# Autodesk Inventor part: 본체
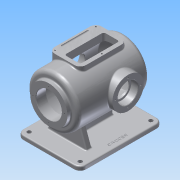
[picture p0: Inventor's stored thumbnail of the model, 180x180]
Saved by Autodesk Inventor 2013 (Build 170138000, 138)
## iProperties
Created: 2016-02
Part Number: 본체
Material: 알루미늄 6061
Document SubType Name: Modeling
Designer: mduedu
Density: 2.71 g/cm^3
Mass: 3760.55 g
Surface Area: 2685.54 cm^2
Volume: 1387.66 cm^3
Author: mduedu
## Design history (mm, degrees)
sketch "스케치2"
  geometry: L1 (0, 100)-(0, -100); L2 (65, -75.993)-(65, 100); L3 (65, 100)-(0, 100); A1 r 100 centre (0, 0) between (0, -100) and (65, -75.993); 2 further points
  constraints: 6 end point, 2 midpoint, 2 point on circle, 1 centre point, 1 coincident, 1 horizontal, 1 parallel, 1 vertical
  dimensions: "d3" = 200 distance of L1.start L1.end; "d5" = 130 diameter of L2 L1; "d6" = 100 radius of A1
revolve "회전1" sketch "스케치2" stored, may be unused: angle "d7" = 90 deg
sketch "스케치3"
  geometry: C1 r 47.5 at (0, 0); 1 further point
  constraints: 1 centre point, 1 coincident
  dimensions: "d8" = 95 diameter of C1
extrude "돌출2" join sketch "스케치3" distance "d10" = 10; taper "d11" = 0 deg
sketch "스케치5"
  geometry: L1 (47.5, 110)-(47.5, 100) reference; L2 (47.5, 100)-(65, 100) reference; L3 (65, 100)-(65, -75.993) reference; L4 (-65, -75.993)-(-65, 100) reference; L5 (-65, 100)-(-47.5, 100) reference; L6 (-47.5, 100)-(-47.5, 110) reference; L7 (-47.5, 110)-(47.5, 110) reference; L8 (55, 85)-(55, -71.239); L9 (0, 85)-(55, 85); L10 (0, 85)-(0, -90); A1 r 100 centre (0, 0) between (0, -100) and (65, -75.993) reference; A2 r 100 centre (0, 0) between (-65, -75.993) and (0, -100) reference; A3 r 90 centre (0, 0) between (0, -90) and (55, -71.239); 1 further point
  constraints: 6 end point, 2 point on circle, 1 centre point, 1 parallel, 1 perpendicular, 1 point on line, 1 vertical
  dimensions: "d13" = 10 distance between parallel lines of L3 L8; "d14" = 10 radial gap between concentric circles of A3 A1; "d15" = 15 distance between parallel lines of L9 L2
revolve "회전2" sketch "스케치5" stored, may be unused: angle "d16" = 90 deg
hole "구멍1" diameter "d19" = 65; stored, may be unused: countersink angle "d23" = 90 deg, drill point angle "d25" = 118 deg; dims "d17" = 10, "d18" = 10, "d20" = 6, "d21" = 4, "d22" = 2, "d24" = 8
node "작업 평면1"
sketch "스케치6"
  geometry: L1 (47.5, 110)-(-47.5, 110) reference; C1 r 40 at (0, -17); 1 further point
  constraints: 1 centre point, 1 vertical alignment
  dimensions: "d27" = 80 diameter of C1; "d29" = 127 distance from line of C1.centre L1
extrude "돌출3" join sketch "스케치6" stored distance "d30" = 10; taper "d31" = 0 deg
hole "구멍2" diameter "d34" = 42; stored, may be unused: countersink angle "d38" = 90 deg, drill point angle "d40" = 118 deg; dims "d32" = 10, "d33" = 10, "d35" = 6, "d36" = 52, "d37" = 18, "d39" = 8
sketch "스케치7" dims "d41" = 65
  geometry: C1 r 40 at (0, 0) reference; 3 further points
  constraints: 2 vertical alignment, 1 coincident, 2 other
hole "구멍3" sketch "스케치7" at (0, 32.5) diameter "d43" = 3.242; stored, may be unused: countersink angle "d47" = 90 deg, drill point angle "d49" = 118 deg; dims "d44" = 11, "d45" = 13, "d46" = 18, "d48" = 13
sketch "스케치8" dims "d53" = 80
  geometry: 3 further points
  constraints: 2 vertical alignment, 1 coincident, 2 other
hole "구멍4" sketch "스케치8" at (0, 40) diameter "d56" = 3.242; stored, may be unused: countersink angle "d60" = 90 deg, drill point angle "d62" = 118 deg; dims "d57" = 11, "d58" = 13, "d59" = 18, "d61" = 13
fillet "모깎기1" dims "d66" = 10
fillet "모깎기2" dims "d67" = 3
fillet "모깎기3" dims "d68" = 0.3
chamfer "모따기1" distance "d69" = 1; stored, may be unused: second distance "d70" = 2, angle "d71" = 45 deg
node "작업 평면5"
sketch "스케치10"
  geometry: L1 (-50, 0)-(50, 0); L2 (-50, 64)-(50, 64); L3 (50, 64)-(50, 50); L4 (50, 50)-(-50, 50); L5 (-50, 50)-(-50, 64); 3 further points
  constraints: 10 end point, 2 horizontal, 2 midpoint, 2 vertical, 1 coincident, 1 vertical alignment
  dimensions: "d132" = 100 distance of L1.start L1.end; "d158" = 50 distance between parallel lines of L4 L1; "d159" = 14 distance of L2.end L3.end; "d160" = 100 distance of L2.start L2.end
extrude "돌출5" join sketch "스케치10" stored distance "d84" = 10; taper "d85" = 0 deg
feature "면 기울기3" dims angle "d135" = 20 deg
sketch "스케치11"
  geometry: L1 (-100, 64)-(-100, 50) reference; L2 (-100, 50)-(-100, -50); L3 (-65, 90)-(-65, -71.239) reference; L4 (-100, -50)-(-65, -50); L5 (-100, 50)-(-55.515, 50) reference; 1 further point
  constraints: 4 end point, 1 collinear, 1 perpendicular, 1 point on line
  dimensions: "d161" = 100 distance between parallel lines of L4 L5
feature "리브1" sketch "스케치11" dims "d88" = 1, "d89" = 8, "d90" = 0, "d91" = 0, "d92" = 1, "d93" = 1
fillet "모깎기5" dims "d103" = 3
fillet "모깎기6" dims "d105" = 3
node "작업 평면6"
sketch "스케치15"
  geometry: L1 (-30, 60)-(50, 60); L2 (50, 60)-(50, -60); L3 (50, -60)-(-30, -60); L4 (-30, -60)-(-30, 60); 3 further points
  constraints: 8 end point, 2 parallel, 1 horizontal, 1 horizontal alignment, 1 midpoint, 1 perpendicular, 1 vertical alignment
  dimensions: "d110" = 80 distance of L2.end L3.end; "d112" = 60 distance from line of L3 point (10, 0); "d113" = 120 distance of L1.end L2.end; "d149" = 30 distance from line of L4 point (0, 0)
extrude "돌출8" join sketch "스케치15" stored distance "d114" = 10; taper "d115" = 0 deg
fillet "모깎기7" dims "d116" = 15
sketch "스케치16"
  geometry: L1 (-30, -45)-(-30, 45) reference; L2 (-15, 60)-(35, 60) reference; L3 (35, -60)-(-15, -60) reference; L4 (-20, -45)-(-20, 45); L5 (-15, 50)-(15, 50); L6 (20, 45)-(20, -45); L7 (15, -50)-(-15, -50); L8 (50, 45)-(50, -45) reference; A1 r 15 centre (-15, -45) between (-30, -45) and (-15, -60) reference; A2 r 15 centre (-15, 45) between (-15, 60) and (-30, 45) reference; A3 r 5 centre (-15, -45) between (-20, -45) and (-15, -50); A4 r 5 centre (-15, 45) between (-15, 50) and (-20, 45); A5 r 5 centre (15, 45) between (20, 45) and (15, 50); A6 r 5 centre (15, -45) between (15, -50) and (20, -45); A7 r 15 centre (35, 45) between (50, 45) and (35, 60) reference; A8 r 15 centre (35, -45) between (35, -60) and (50, -45) reference
  constraints: 8 end point, 8 point on circle, 4 centre point, 2 equal radius, 3 other
  dimensions: "d137" = 10 distance between parallel lines of L4 L1; "d150" = 40 distance between parallel lines of L6 L4; "d151" = 100 distance between parallel lines of L7 L5
extrude "돌출9" cut sketch "스케치16" stored distance "d118" = 10; taper "d119" = 0 deg
fillet "모깎기8" dims "d120" = 3
sketch "스케치17"
  geometry: L1 (-30, -45)-(-30, 45) reference; L2 (-20, 45)-(-20, -45) reference; L3 (-15, -50)-(15, -50) reference; L4 (20, -45)-(20, 45) reference; L5 (15, 50)-(-15, 50) reference; L6 (-15, 60)-(35, 60) reference; L7 (35, -60)-(-15, -60) reference; L8 (15, 55)-(-15, 55); L9 (-25, 45)-(-25, -45); L10 (-15, -55)-(15, -55); L11 (25, -45)-(25, 45); L12 (50, 45)-(50, -45) reference; L13 (35, 55)-(-15, 55); L14 (-25, 45)-(-25, -45); L15 (-15, -55)-(35, -55); L16 (45, -45)-(45, 45); A1 r 5 centre (-15, 45) between (-15, 50) and (-20, 45) reference; A2 r 5 centre (-15, -45) between (-20, -45) and (-15, -50) reference; A3 r 5 centre (15, -45) between (15, -50) and (20, -45) reference; A4 r 5 centre (15, 45) between (20, 45) and (15, 50) reference; A5 r 15 centre (-15, 45) between (-15, 60) and (-30, 45) reference; A6 r 15 centre (-15, -45) between (-30, -45) and (-15, -60) reference; A7 r 10 centre (-15, 45) between (-15, 55) and (-25, 45); A8 r 10 centre (-15, -45) between (-25, -45) and (-15, -55); A9 r 10 centre (15, -45) between (15, -55) and (25, -45); A10 r 10 centre (15, 45) between (25, 45) and (15, 55); A11 r 15 centre (35, 45) between (50, 45) and (35, 60) reference; A12 r 15 centre (35, -45) between (35, -60) and (50, -45) reference; A13 r 10 centre (-15, 45) between (-15, 55) and (-25, 45); A14 r 10 centre (-15, -45) between (-25, -45) and (-15, -55); A15 r 10 centre (35, -45) between (35, -55) and (45, -45); A16 r 10 centre (35, 45) between (45, 45) and (35, 55); 6 further points
  constraints: 18 point on circle, 16 end point, 8 centre point, 4 midpoint, 4 tangent, 11 other
  dimensions: "d138" = 5 distance between parallel lines of L8 L6; "d157" = 5 distance between parallel lines of L12 L16
hole "구멍5" sketch "스케치17" at (-25, 0), (42.071, 52.071), (42.071, -52.071) diameter "d122" = 3.242; stored, may be unused: countersink angle "d126" = 90 deg, drill point angle "d128" = 118 deg; dims "d123" = 9, "d124" = 13, "d125" = 18, "d127" = 11
sketch "스케치19"
  geometry: L1 (-50, 70)-(-35, 70) reference; L2 (-50, 42.603)-(-50, 70) reference; C1 r 2.5 at (-43, 70); 1 further point
  constraints: 1 centre point, 1 point on line
  dimensions: "d152" = 5 diameter of C1; "d153" = 7 distance from line of C1.centre L2
extrude "돌출11" cut sketch "스케치19" stored distance "d154" = 70; taper "d155" = 0 deg
fillet "모깎기11" dims "d156" = 2.5
sketch "스케치20"
  geometry: L1 (-80, 110)-(80, 110); L2 (80, 110)-(80, -100); L3 (80, -100)-(-80, -100); L4 (-80, -100)-(-80, 110); 2 further points
  constraints: 8 end point, 2 parallel, 1 horizontal, 1 midpoint, 1 perpendicular, 1 vertical alignment
  dimensions: "d162" = 160 distance of L1.start L1.end; "d164" = 210 distance of L1.end L2.end; "d165" = 110 distance from line of L1 point (0, 0)
extrude "돌출12" join sketch "스케치20" distance "d166" = 10; taper "d167" = 0 deg
fillet "모깎기12" dims "d168" = 15
fillet "모깎기13" dims "d169" = 3
fillet "모깎기14" dims "d170" = 3
sketch "스케치21"
  geometry: C1 r 5 at (-65, -95); C2 r 5 at (65, -95); C3 r 5 at (65, 85); C4 r 5 at (-65, 85); A1 r 15 centre (-65, -95) between (-80, -95) and (-65, -110) reference; A2 r 15 centre (-65, 85) between (-65, 100) and (-80, 85) reference; A3 r 15 centre (65, 85) between (80, 85) and (65, 100) reference; A4 r 15 centre (65, -95) between (65, -110) and (80, -95) reference; 1 further point
  constraints: 4 centre point, 4 coincident, 3 equal radius
  dimensions: "d171" = 10 diameter of C1
extrude "돌출13" cut sketch "스케치21" stored distance "d172" = 10; taper "d173" = 0 deg
sketch "스케치22"
  geometry: L1 (80, -95)-(80, 85) reference; 2 further points
  constraints: 1 horizontal alignment, 1 other
  dimensions: "d174" = 15 distance from line of L1 point (65, 0)
feature "엠보싱2" sketch "스케치22" dims "d13" = 10, "d175" = 0.5, "d176" = 0
node "솔리드2"
pattern_circular "원형 패턴1" dims angle "d51" = 360 deg
mirror "대칭1"
pattern_circular "원형 패턴2" dims angle "d64" = 360 deg
node "절단 모서리 투영1"
node "절단 모서리 투영2"
node "절단 모서리 투영3"
other parameters: "d26" = 75
